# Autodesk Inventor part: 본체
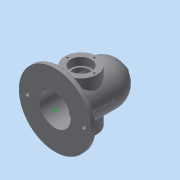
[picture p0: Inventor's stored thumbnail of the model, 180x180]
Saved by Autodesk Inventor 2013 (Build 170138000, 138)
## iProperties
Created: 2019-11
Part Number: 본체
Material: Generic
Document SubType Name: Modeling
Designer: Administrator
Density: 1 g/cm^3
Author: Administrator
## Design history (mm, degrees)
sketch "스케치1"
  geometry: 1 further point
sketch "스케치2"
  geometry: C1 r 70 at (0, 0); 1 further point
  constraints: 1 centre point, 1 coincident
  dimensions: "d0" = 140 diameter of C1
extrude "돌출1" new body sketch "스케치2" distance "d2" = 10; taper "d3" = 0 deg
sketch "스케치3"
  geometry: C1 r 70 at (0, 0) reference; C2 r 40 at (0, 0)
  constraints: 1 centre point, 1 coincident
  dimensions: "d4" = 80 diameter of C2
extrude "돌출2" join sketch "스케치3" distance "d6" = 80; taper "d7" = 0 deg
sketch "스케치4"
  geometry: L1 (0, 70)-(0, -70) reference; L2 (130, 0)-(50, 0); A1 r 40 centre (90, 0) between (130, 0) and (50, 0); 2 further points
  constraints: 2 end point, 2 point on circle, 1 centre point, 1 coincident, 1 perpendicular
  dimensions: "d8" = 90 distance from line of L1 point (90, 0); "d10" = 80 diameter of A1
revolve "회전1" sketch "스케치4" stored, may be unused: angle "d11" = 90 deg
sketch "스케치5"
  geometry: L1 (-70, 0)-(70, 0) reference; C1 r 31 at (0, 50); 2 further points
  constraints: 1 centre point, 1 coincident
  dimensions: "d12" = 50 distance from line of L1 point (0, 50); "d13" = 62 diameter of C1
extrude "돌출3" join sketch "스케치5" stored distance "d14" = 100; taper "d15" = 0 deg
node "작업 평면2"
sketch "스케치6"
  geometry: C1 r 7.5 at (0, 0); 1 further point
  constraints: 1 centre point, 1 coincident
  dimensions: "d18" = 15 diameter of C1
extrude "돌출4" join sketch "스케치6" stored distance "d20" = 100; taper "d21" = 0 deg
sketch "스케치7"
  geometry: C1 r 7.5 at (0, 0) reference; 1 further point
  constraints: 1 coincident
hole "구멍1" sketch "스케치7" at (0, 0) diameter "d22" = 5.188; stored, may be unused: countersink angle "d26" = 90 deg, drill point angle "d28" = 118 deg; dims "d23" = 6, "d24" = 4, "d25" = 2, "d27" = 8
fillet "모깎기1" dims "d29" = 3
sketch "스케치8"
  geometry: C1 r 31 at (0, 0) reference; C2 r 16.5 at (0, 0); 1 further point
  constraints: 1 centre point, 1 coincident
  dimensions: "d30" = 33 diameter of C2
extrude "돌출5" cut sketch "스케치8" distance "d32" = 100; taper "d33" = 0 deg
sketch "스케치9"
  geometry: C1 r 2.594 at (0, 0) reference; C2 r 70 at (0, 0) reference; C3 r 30 at (0, 0)
  constraints: 1 centre point, 1 coincident
  dimensions: "d34" = 60 diameter of C3
extrude "돌출6" cut sketch "스케치9" distance "d36" = 90; taper "d37" = 0 deg
sketch "스케치11"
  geometry: L1 (0, 70)-(0, -70) reference; L2 (60, 0)-(120, 0); A1 r 30 centre (90, 0) between (120, 0) and (60, 0); 2 further points
  constraints: 2 end point, 2 point on circle, 1 centre point, 1 coincident, 1 perpendicular
  dimensions: "d38" = 90 distance from line of L1 point (90, 0); "d39" = 60 diameter of A1
revolve "회전2" sketch "스케치11" stored, may be unused: angle "d40" = 90 deg
sketch "스케치12"
  geometry: C1 r 31 at (0, 0) reference; C2 r 20 at (0, 0); 1 further point
  constraints: 1 centre point, 1 coincident
  dimensions: "d41" = 40 diameter of C2
extrude "돌출7" cut sketch "스케치12" distance "d43" = 15; taper "d44" = 0 deg
sketch "스케치13"
  geometry: C1 r 31 at (0, 0) reference; C2 r 20 at (0, 0); 1 further point
  constraints: 1 centre point, 1 coincident
  dimensions: "d45" = 40 diameter of C2
extrude "돌출8" cut sketch "스케치13" distance "d47" = 15; taper "d48" = 0 deg
sketch "스케치14" dims "d49" = 52
  geometry: C1 r 31 at (0, 0) reference; C2 r 2 at (0, -26); 2 further points
  constraints: 2 vertical alignment, 1 centre point, 1 coincident, 2 other
  dimensions: "d51" = 4 diameter of C2
hole "구멍2" sketch "스케치14" at (0, -26) diameter "d52" = 3.242; stored, may be unused: countersink angle "d56" = 90 deg, drill point angle "d58" = 118 deg; dims "d53" = 6, "d54" = 4, "d55" = 2, "d57" = 8
sketch "스케치15" dims "d63" = 110
  geometry: C1 r 40 at (0, 0) reference; C2 r 70 at (0, 0) reference; C3 r 4.5 at (-55, 0); 1 further point
  constraints: 2 horizontal alignment, 1 centre point, 1 coincident, 2 other
  dimensions: "d62" = 9 diameter of C3
extrude "돌출9" cut sketch "스케치15" distance "d64" = 15; taper "d65" = 0 deg
node "작업 평면3"
sketch "스케치18"
  geometry: L1 (0, 70)-(0, -70) reference; 2 further points
  constraints: 1 horizontal alignment, 1 other
  dimensions: "d67" = 50 distance from line of L1 point (50, 0)
feature "엠보싱1" sketch "스케치18" dims "d12" = 50, "d13" = 62, "d68" = 0.5, "d69" = 0
fillet "모깎기2" dims "d70" = 3
fillet "모깎기3" dims "d71" = 3
node "솔리드1"
pattern_circular "원형 패턴1" dims angle "d60" = 360 deg
mirror "대칭1"
mirror "대칭2"
other parameters: "d17" = -135
